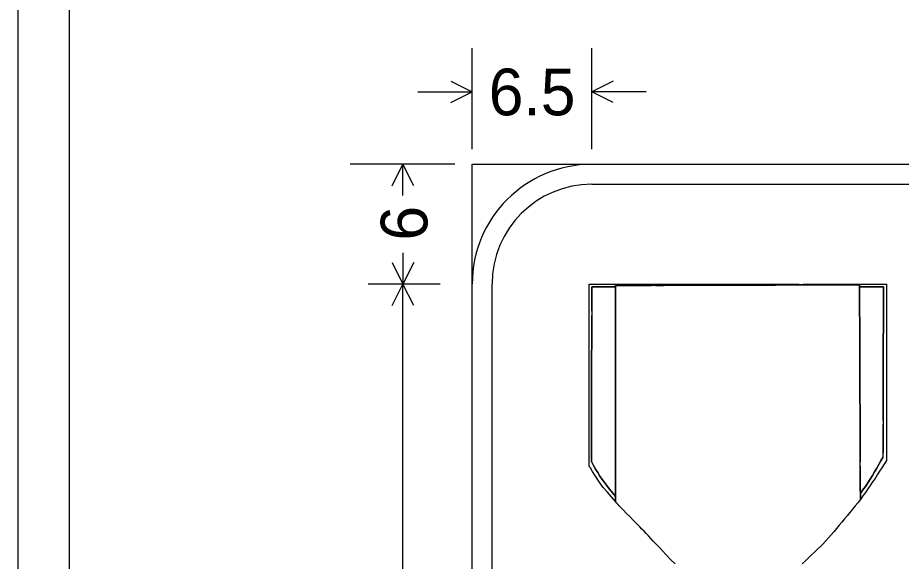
# Model space of a CAD drawing. Extents: x 187716 to 188418, y 178603 to 179533.
# Drawn here: x 187716 to 187905.3, y 179178.8 to 179295.2 of the extents above; entities that cross this region are included whole.
import ezdxf

# ---------------------------------------------------------------- set-up
doc = ezdxf.new("R2010")
doc.units = 0
doc.layers.add('Default', color=7, linetype='Continuous')

msp = doc.modelspace()

# ---------------------------------------------------------------- linework, layer by layer
at = {"layer": 'Default'}
for p, q in [((187813.36, 179267.08), (187813.36, 179288.69)), ((187839, 179267.08), (187839, 179288.69)), ((187808.77, 179281.65), (187813.36, 179279.35)), ((187843.59, 179281.65), (187839, 179279.35)), ((187801.71, 179279.35), (187813.36, 179279.35)), ((187808.77, 179277.06), (187813.36, 179279.35)), ((187850.64, 179279.35), (187839, 179279.35)), ((187843.59, 179277.06), (187839, 179279.35)), ((187809.67, 179263.83), (187787.24, 179263.83)), ((187806.47, 179263.83), (187791.08, 179263.83)), ((187796.24, 179259.24), (187798.53, 179263.83)), ((187798.53, 179257.15), (187798.53, 179263.83)), ((187800.83, 179259.24), (187798.53, 179263.83)), ((187813.36, 179263.83), (188326.2, 179263.83)), ((187813.36, 179058.69), (187813.36, 179263.83)), ((187839, 179263.83), (188300.55, 179263.83)), ((187839, 179259.55), (188300.55, 179259.55)), ((187798.53, 179244.86), (187798.53, 179238.18)), ((187796.24, 179242.77), (187798.53, 179238.18)), ((187800.83, 179242.77), (187798.53, 179238.18)), ((187806.47, 179238.18), (187791.08, 179238.18)), ((187796.24, 179233.6), (187798.53, 179238.18)), ((187798.53, 179173.47), (187798.53, 179238.18)), ((187800.83, 179233.6), (187798.53, 179238.18)), ((187813.36, 179084.33), (187813.36, 179238.18)), ((187817.63, 179084.33), (187817.63, 179238.18))]:
    msp.add_line(p, q, dxfattribs=at)
for points in [[(188418.09, 178602.69), (188418.09, 179533.02), (187715.97, 179533.02), (187715.97, 178602.69)], [(188407.12, 178613.73), (188407.12, 179522.02), (187727.02, 179522.02), (187727.02, 178613.73)], [(187813.36, 179263.83), (188326.2, 179263.83), (188326.2, 179058.69), (187813.36, 179058.69)]]:
    msp.add_lwpolyline(points, close=True, dxfattribs=at)
for points in [[(187838.46, 179199.13), (187838.46, 179199.99), (187838.46, 179200.86), (187838.46, 179201.73), (187838.46, 179202.6), (187838.46, 179203.47), (187838.46, 179204.34), (187838.46, 179205.2), (187838.46, 179206.07), (187838.46, 179206.94), (187838.46, 179207.81), (187838.46, 179208.68), (187838.46, 179209.54), (187838.46, 179210.41), (187838.46, 179211.28), (187838.46, 179212.15), (187838.46, 179213.02), (187838.46, 179213.88), (187838.46, 179214.75), (187838.46, 179215.62), (187838.46, 179216.49), (187838.46, 179217.36), (187838.46, 179218.22), (187838.46, 179219.09), (187838.46, 179219.96), (187838.46, 179220.83), (187838.46, 179221.7), (187838.46, 179222.56), (187838.46, 179223.43), (187838.46, 179224.3), (187838.46, 179225.17), (187838.46, 179226.04), (187838.46, 179226.9), (187838.46, 179227.77), (187838.46, 179228.64), (187838.46, 179229.51), (187838.46, 179230.37), (187838.46, 179231.24), (187838.46, 179232.11), (187838.46, 179232.98), (187838.46, 179233.85), (187838.46, 179234.71), (187838.46, 179235.58), (187838.46, 179236.45), (187838.46, 179237.32), (187838.46, 179238.18), (187838.46, 179238.18), (187839.3, 179238.18), (187840.15, 179238.18), (187841, 179238.18), (187841.85, 179238.18), (187842.7, 179238.18), (187843.55, 179238.18), (187844.4, 179238.18), (187845.24, 179238.18), (187846.09, 179238.18), (187846.94, 179238.18), (187847.79, 179238.18), (187848.64, 179238.18), (187849.49, 179238.18), (187850.33, 179238.18), (187851.18, 179238.18), (187852.03, 179238.18), (187852.88, 179238.18), (187853.73, 179238.18), (187854.58, 179238.18), (187855.43, 179238.18), (187856.27, 179238.18), (187857.12, 179238.18), (187857.97, 179238.18), (187858.82, 179238.18), (187859.67, 179238.18), (187860.52, 179238.18), (187861.37, 179238.18), (187862.21, 179238.18), (187863.06, 179238.18), (187863.91, 179238.18), (187864.76, 179238.18), (187865.61, 179238.18), (187866.46, 179238.18), (187867.31, 179238.18), (187868.16, 179238.18), (187869, 179238.18), (187869.85, 179238.18), (187870.7, 179238.18), (187871.55, 179238.18), (187872.4, 179238.18), (187873.25, 179238.18), (187874.1, 179238.18), (187874.94, 179238.18), (187875.79, 179238.18), (187876.64, 179238.18), (187877.49, 179238.18), (187878.34, 179238.18), (187879.19, 179238.18), (187880.04, 179238.18), (187880.89, 179238.18), (187881.73, 179238.18), (187882.58, 179238.18), (187883.43, 179238.18)], [(187846.67, 179237.89), (187845.81, 179237.89), (187844.96, 179237.88), (187844.1, 179237.88), (187844.1, 179237.88), (187844.1, 179237.78), (187844.1, 179237.67), (187844.1, 179237.57), (187843.08, 179237.57), (187842.06, 179237.57), (187841.03, 179237.57), (187840.02, 179237.57), (187839, 179237.57), (187838.99, 179236.7), (187838.99, 179235.83), (187838.99, 179234.96), (187838.99, 179234.09), (187838.99, 179233.23), (187838.98, 179232.36), (187838.98, 179231.49), (187838.98, 179230.62), (187838.98, 179229.75), (187838.98, 179228.88), (187838.97, 179228.01), (187838.97, 179227.14), (187838.97, 179226.28), (187838.97, 179225.41), (187838.97, 179224.54), (187838.96, 179223.67), (187838.96, 179222.8), (187838.96, 179221.93), (187838.96, 179221.06), (187838.96, 179220.19), (187838.95, 179219.33), (187838.95, 179218.46), (187838.95, 179217.59), (187838.95, 179216.72), (187838.95, 179215.85), (187838.94, 179214.98), (187838.94, 179214.11), (187838.94, 179213.24), (187838.94, 179212.37), (187838.94, 179211.5), (187838.93, 179210.64), (187838.93, 179209.77), (187838.93, 179208.9), (187838.93, 179208.03), (187838.93, 179207.16), (187838.92, 179206.29), (187838.92, 179205.42), (187838.92, 179204.55), (187838.92, 179203.68), (187838.92, 179202.81), (187838.91, 179201.95), (187838.91, 179201.08), (187838.91, 179200.21), (187838.91, 179200.21), (187839.35, 179199.38), (187839.8, 179198.58), (187840.27, 179197.82), (187840.75, 179197.07), (187841.24, 179196.34), (187841.76, 179195.63), (187842.3, 179194.91), (187842.87, 179194.19), (187843.47, 179193.45), (187844.1, 179192.7), (187844.1, 179192.34), (187844.1, 179191.98), (187844.1, 179191.62), (187843.22, 179192.63), (187842.34, 179193.63), (187841.46, 179194.64), (187840.6, 179195.84), (187839.81, 179197.04), (187839.16, 179198.08), (187838.69, 179198.82), (187838.46, 179199.13)], [(187844.1, 179237.57), (187844.1, 179236.71), (187844.1, 179235.84), (187844.1, 179234.98), (187844.1, 179234.12), (187844.1, 179233.26), (187844.1, 179232.39), (187844.1, 179231.53), (187844.1, 179230.67), (187844.1, 179229.8), (187844.1, 179228.94), (187844.1, 179228.08), (187844.1, 179227.22), (187844.1, 179226.35), (187844.1, 179225.49), (187844.1, 179224.63), (187844.1, 179223.77), (187844.1, 179222.9), (187844.1, 179222.04), (187844.1, 179221.18), (187844.1, 179220.32), (187844.1, 179219.45), (187844.1, 179218.59), (187844.1, 179217.73), (187844.1, 179216.86), (187844.1, 179216), (187844.1, 179215.14), (187844.1, 179214.28), (187844.1, 179213.41), (187844.1, 179212.55), (187844.1, 179211.69), (187844.1, 179210.82), (187844.1, 179209.96), (187844.1, 179209.1), (187844.1, 179208.24), (187844.1, 179207.37), (187844.1, 179206.51), (187844.1, 179205.65), (187844.1, 179204.78), (187844.1, 179203.92), (187844.1, 179203.06), (187844.1, 179202.2), (187844.1, 179201.33), (187844.1, 179200.47), (187844.1, 179199.61), (187844.1, 179198.74), (187844.1, 179197.88), (187844.1, 179197.02), (187844.1, 179196.15), (187844.1, 179195.29), (187844.1, 179194.43), (187844.1, 179193.57), (187844.1, 179192.7), (187844.1, 179192.7), (187843.47, 179193.45), (187842.87, 179194.19), (187842.3, 179194.91), (187841.76, 179195.63), (187841.24, 179196.34), (187840.75, 179197.07), (187840.27, 179197.82), (187839.8, 179198.58), (187839.35, 179199.38), (187838.91, 179200.21), (187838.91, 179201.08), (187838.91, 179201.95), (187838.92, 179202.81), (187838.92, 179203.68), (187838.92, 179204.55), (187838.92, 179205.42), (187838.92, 179206.29), (187838.93, 179207.16), (187838.93, 179208.03), (187838.93, 179208.9), (187838.93, 179209.77), (187838.93, 179210.64), (187838.94, 179211.5), (187838.94, 179212.37), (187838.94, 179213.24), (187838.94, 179214.11), (187838.94, 179214.98), (187838.95, 179215.85), (187838.95, 179216.72), (187838.95, 179217.59), (187838.95, 179218.46), (187838.95, 179219.33), (187838.96, 179220.19), (187838.96, 179221.06), (187838.96, 179221.93), (187838.96, 179222.8), (187838.96, 179223.67), (187838.97, 179224.54), (187838.97, 179225.41), (187838.97, 179226.28), (187838.97, 179227.14), (187838.97, 179228.01), (187838.98, 179228.88), (187838.98, 179229.75), (187838.98, 179230.62), (187838.98, 179231.49)], [(187838.98, 179232.36), (187838.99, 179233.23), (187838.99, 179234.09), (187838.99, 179234.96), (187838.99, 179235.83), (187838.99, 179236.7), (187839, 179237.57), (187839, 179237.57), (187840.01, 179237.57), (187841.03, 179237.57), (187842.05, 179237.57), (187843.08, 179237.57), (187844.1, 179237.57)], [(187856.83, 179178.32), (187855.86, 179179.25), (187854.95, 179180.21), (187854.14, 179181.08), (187853.42, 179181.85), (187852.76, 179182.54), (187852.17, 179183.17), (187851.63, 179183.75), (187851.12, 179184.28), (187850.65, 179184.78), (187850.18, 179185.26), (187849.73, 179185.74), (187849.26, 179186.22), (187848.78, 179186.71), (187848.27, 179187.24), (187847.71, 179187.8), (187847.11, 179188.42), (187846.44, 179189.1), (187845.7, 179189.85), (187844.87, 179190.69), (187844.87, 179190.69), (187844.61, 179191), (187844.36, 179191.31), (187844.1, 179191.62), (187844.1, 179191.98), (187844.1, 179192.34), (187844.1, 179192.7), (187844.1, 179193.57), (187844.1, 179194.43), (187844.1, 179195.29), (187844.1, 179196.15), (187844.1, 179197.02), (187844.1, 179197.88), (187844.1, 179198.74), (187844.1, 179199.61), (187844.1, 179200.47), (187844.1, 179201.33), (187844.1, 179202.2), (187844.1, 179203.06), (187844.1, 179203.92), (187844.1, 179204.78), (187844.1, 179205.65), (187844.1, 179206.51), (187844.1, 179207.37), (187844.1, 179208.24), (187844.1, 179209.1), (187844.1, 179209.96), (187844.1, 179210.82), (187844.1, 179211.69), (187844.1, 179212.55), (187844.1, 179213.41), (187844.1, 179214.28), (187844.1, 179215.14), (187844.1, 179216), (187844.1, 179216.86), (187844.1, 179217.73), (187844.1, 179218.59), (187844.1, 179219.45), (187844.1, 179220.32), (187844.1, 179221.18), (187844.1, 179222.04), (187844.1, 179222.9), (187844.1, 179223.77), (187844.1, 179224.63), (187844.1, 179225.49), (187844.1, 179226.35), (187844.1, 179227.22), (187844.1, 179228.08), (187844.1, 179228.94), (187844.1, 179229.8), (187844.1, 179230.67), (187844.1, 179231.53), (187844.1, 179232.39), (187844.1, 179233.26), (187844.1, 179234.12), (187844.1, 179234.98), (187844.1, 179235.84), (187844.1, 179236.71), (187844.1, 179237.57), (187844.1, 179237.57), (187844.1, 179237.67), (187844.1, 179237.78), (187844.1, 179237.88), (187844.96, 179237.88), (187845.81, 179237.89), (187846.67, 179237.89), (187847.53, 179237.89), (187848.38, 179237.9), (187849.24, 179237.9), (187850.1, 179237.9), (187850.95, 179237.9), (187851.81, 179237.91)], [(187901.42, 179209.01), (187901.42, 179209.87), (187901.43, 179210.74), (187901.43, 179211.6), (187901.43, 179212.47), (187901.43, 179213.33), (187901.43, 179214.2), (187901.44, 179215.07), (187901.44, 179215.93), (187901.44, 179216.8), (187901.44, 179217.66), (187901.44, 179218.53), (187901.45, 179219.39), (187901.45, 179220.26), (187901.45, 179221.12), (187901.45, 179221.99), (187901.45, 179222.86), (187901.46, 179223.72), (187901.46, 179224.59), (187901.46, 179225.45), (187901.46, 179226.32), (187901.46, 179227.18), (187901.47, 179228.05), (187901.47, 179228.91), (187901.47, 179229.78), (187901.47, 179230.65), (187901.48, 179231.51), (187901.48, 179232.38), (187901.48, 179233.24), (187901.48, 179234.11), (187901.48, 179234.97), (187901.48, 179235.84), (187901.49, 179236.7), (187901.49, 179237.57), (187901.49, 179237.57), (187900.46, 179237.57), (187899.44, 179237.57), (187898.42, 179237.57), (187897.4, 179237.57), (187896.38, 179237.57), (187896.38, 179237.73), (187896.38, 179237.88), (187896.38, 179238.03), (187895.52, 179238.03), (187894.66, 179238.03), (187893.8, 179238.03), (187892.95, 179238.02), (187892.09, 179238.02), (187891.23, 179238.02), (187890.38, 179238.02), (187889.52, 179238.01), (187888.66, 179238.01), (187887.8, 179238.01), (187886.95, 179238.01), (187886.09, 179238.01), (187885.23, 179238), (187884.38, 179238), (187883.52, 179238), (187882.66, 179238), (187881.8, 179237.99), (187880.95, 179237.99), (187880.09, 179237.99), (187879.23, 179237.99), (187878.38, 179237.98), (187877.52, 179237.98), (187876.66, 179237.98), (187875.81, 179237.98), (187874.95, 179237.97), (187874.09, 179237.97), (187873.23, 179237.97), (187872.38, 179237.97), (187871.52, 179237.96), (187870.66, 179237.96), (187869.81, 179237.96), (187868.95, 179237.96), (187868.09, 179237.95), (187867.23, 179237.95), (187866.38, 179237.95), (187865.52, 179237.95), (187864.66, 179237.94), (187863.81, 179237.94), (187862.95, 179237.94), (187862.09, 179237.94), (187861.24, 179237.93), (187860.38, 179237.93), (187859.52, 179237.93), (187858.67, 179237.93), (187857.81, 179237.92), (187856.95, 179237.92), (187856.09, 179237.92), (187855.24, 179237.92), (187854.38, 179237.91), (187853.52, 179237.91), (187852.67, 179237.91), (187851.81, 179237.91), (187850.95, 179237.9), (187850.1, 179237.9), (187849.24, 179237.9), (187848.38, 179237.9), (187847.53, 179237.89)], [(187852.67, 179237.91), (187853.52, 179237.91), (187854.38, 179237.91), (187855.24, 179237.92), (187856.09, 179237.92), (187856.95, 179237.92), (187857.81, 179237.92), (187858.67, 179237.93), (187859.52, 179237.93), (187860.38, 179237.93), (187861.24, 179237.93), (187862.09, 179237.94), (187862.95, 179237.94), (187863.81, 179237.94), (187864.66, 179237.94), (187865.52, 179237.95), (187866.38, 179237.95), (187867.23, 179237.95), (187868.09, 179237.95), (187868.95, 179237.96), (187869.81, 179237.96), (187870.66, 179237.96), (187871.52, 179237.96), (187872.38, 179237.97), (187873.23, 179237.97), (187874.09, 179237.97), (187874.95, 179237.97), (187875.81, 179237.98), (187876.66, 179237.98), (187877.52, 179237.98), (187878.38, 179237.98), (187879.23, 179237.99), (187880.09, 179237.99), (187880.95, 179237.99), (187881.8, 179237.99), (187882.66, 179238), (187883.52, 179238), (187884.38, 179238), (187885.23, 179238), (187886.09, 179238.01), (187886.95, 179238.01), (187887.8, 179238.01), (187888.66, 179238.01), (187889.52, 179238.01), (187890.38, 179238.02), (187891.23, 179238.02), (187892.09, 179238.02), (187892.95, 179238.02), (187893.8, 179238.03), (187894.66, 179238.03), (187895.52, 179238.03), (187896.38, 179238.03), (187896.38, 179238.03), (187896.38, 179237.88), (187896.38, 179237.73), (187896.38, 179237.57), (187896.38, 179236.72), (187896.38, 179235.87), (187896.38, 179235.02), (187896.39, 179234.17), (187896.39, 179233.31), (187896.39, 179232.46), (187896.39, 179231.61), (187896.4, 179230.76), (187896.4, 179229.91), (187896.4, 179229.06), (187896.41, 179228.21), (187896.41, 179227.36), (187896.41, 179226.51), (187896.42, 179225.66), (187896.42, 179224.81), (187896.42, 179223.96), (187896.42, 179223.11), (187896.43, 179222.25), (187896.43, 179221.4), (187896.43, 179220.55), (187896.44, 179219.7), (187896.44, 179218.85), (187896.44, 179218), (187896.45, 179217.15), (187896.45, 179216.3), (187896.45, 179215.45), (187896.46, 179214.6), (187896.46, 179213.75), (187896.46, 179212.89), (187896.47, 179212.04), (187896.47, 179211.19), (187896.47, 179210.34), (187896.47, 179209.49), (187896.48, 179208.64), (187896.48, 179207.79), (187896.48, 179206.94), (187896.49, 179206.09), (187896.49, 179205.24), (187896.49, 179204.38), (187896.5, 179203.53), (187896.5, 179202.68), (187896.5, 179201.83), (187896.51, 179200.98), (187896.51, 179200.13)], [(187884.28, 179238.18), (187885.13, 179238.18), (187885.98, 179238.18), (187886.83, 179238.18), (187887.68, 179238.18), (187888.52, 179238.18), (187889.37, 179238.18), (187890.22, 179238.18), (187891.07, 179238.18), (187891.92, 179238.18), (187892.77, 179238.18), (187893.62, 179238.18), (187894.47, 179238.18), (187895.31, 179238.18), (187896.16, 179238.18), (187897.01, 179238.18), (187897.86, 179238.18), (187898.71, 179238.18), (187899.56, 179238.18), (187900.41, 179238.18), (187901.26, 179238.18), (187902.11, 179238.18), (187902.11, 179238.18), (187902.11, 179237.33), (187902.11, 179236.47), (187902.11, 179235.61), (187902.11, 179234.75), (187902.11, 179233.9), (187902.11, 179233.04), (187902.11, 179232.18), (187902.11, 179231.32), (187902.11, 179230.46), (187902.11, 179229.61), (187902.11, 179228.75), (187902.11, 179227.89), (187902.11, 179227.03), (187902.11, 179226.18), (187902.11, 179225.32), (187902.11, 179224.46), (187902.11, 179223.6), (187902.11, 179222.75), (187902.11, 179221.89), (187902.11, 179221.03), (187902.11, 179220.17), (187902.11, 179219.31), (187902.11, 179218.46), (187902.11, 179217.6), (187902.11, 179216.74), (187902.11, 179215.88), (187902.11, 179215.03), (187902.11, 179214.17), (187902.11, 179213.31), (187902.11, 179212.45), (187902.11, 179211.59), (187902.11, 179210.74), (187902.11, 179209.88), (187902.11, 179209.02), (187902.11, 179208.16), (187902.11, 179207.31), (187902.11, 179206.45), (187902.11, 179205.59), (187902.11, 179204.73), (187902.11, 179203.88), (187902.11, 179203.02), (187902.11, 179202.16), (187902.11, 179201.3), (187902.11, 179200.44), (187902.11, 179200.44), (187901.63, 179199.66), (187901.15, 179198.88), (187900.66, 179198.11), (187900.17, 179197.34), (187899.68, 179196.59), (187899.17, 179195.83), (187898.66, 179195.08), (187898.14, 179194.33), (187897.62, 179193.58), (187897.08, 179192.84), (187896.54, 179192.09), (187896.54, 179192.5), (187896.54, 179192.91), (187896.54, 179193.32), (187897.08, 179194.11), (187897.61, 179194.88), (187898.12, 179195.65), (187898.62, 179196.42), (187899.11, 179197.19), (187899.59, 179197.96), (187900.06, 179198.75), (187900.51, 179199.55), (187900.96, 179200.37), (187901.4, 179201.21), (187901.41, 179202.08), (187901.41, 179202.94), (187901.41, 179203.81), (187901.41, 179204.68), (187901.41, 179205.54), (187901.42, 179206.41), (187901.42, 179207.27), (187901.42, 179208.14)], [(187896.54, 179193.32), (187896.53, 179194.17), (187896.53, 179195.02), (187896.53, 179195.87), (187896.52, 179196.72), (187896.52, 179197.58), (187896.52, 179198.43), (187896.51, 179199.28), (187896.51, 179200.13), (187896.51, 179200.98), (187896.5, 179201.83), (187896.5, 179202.68), (187896.5, 179203.53), (187896.49, 179204.38), (187896.49, 179205.24), (187896.49, 179206.09), (187896.48, 179206.94), (187896.48, 179207.79), (187896.48, 179208.64), (187896.47, 179209.49), (187896.47, 179210.34), (187896.47, 179211.19), (187896.47, 179212.04), (187896.46, 179212.89), (187896.46, 179213.75), (187896.46, 179214.6), (187896.45, 179215.45), (187896.45, 179216.3), (187896.45, 179217.15), (187896.44, 179218), (187896.44, 179218.85), (187896.44, 179219.7), (187896.43, 179220.55), (187896.43, 179221.4), (187896.43, 179222.25), (187896.42, 179223.11), (187896.42, 179223.96), (187896.42, 179224.81), (187896.42, 179225.66), (187896.41, 179226.51), (187896.41, 179227.36), (187896.41, 179228.21), (187896.4, 179229.06), (187896.4, 179229.91), (187896.4, 179230.76), (187896.39, 179231.61), (187896.39, 179232.46), (187896.39, 179233.31), (187896.39, 179234.17), (187896.38, 179235.02), (187896.38, 179235.87), (187896.38, 179236.72), (187896.38, 179237.57), (187896.38, 179237.57), (187897.4, 179237.57), (187898.42, 179237.57), (187899.44, 179237.57), (187900.46, 179237.57), (187901.49, 179237.57), (187901.49, 179236.7), (187901.48, 179235.84), (187901.48, 179234.97), (187901.48, 179234.11), (187901.48, 179233.24), (187901.48, 179232.38), (187901.48, 179231.51), (187901.47, 179230.65), (187901.47, 179229.78), (187901.47, 179228.91), (187901.47, 179228.05), (187901.46, 179227.18), (187901.46, 179226.32), (187901.46, 179225.45), (187901.46, 179224.59), (187901.46, 179223.72), (187901.45, 179222.86), (187901.45, 179221.99), (187901.45, 179221.12), (187901.45, 179220.26), (187901.45, 179219.39), (187901.44, 179218.53), (187901.44, 179217.66), (187901.44, 179216.8), (187901.44, 179215.93), (187901.44, 179215.07), (187901.43, 179214.2), (187901.43, 179213.33), (187901.43, 179212.47), (187901.43, 179211.6), (187901.43, 179210.74), (187901.42, 179209.87), (187901.42, 179209.01), (187901.42, 179208.14), (187901.42, 179207.27), (187901.42, 179206.41), (187901.41, 179205.54), (187901.41, 179204.68), (187901.41, 179203.81), (187901.41, 179202.94), (187901.41, 179202.08)], [(187901.4, 179201.21), (187901.4, 179201.21), (187900.96, 179200.37), (187900.51, 179199.55), (187900.06, 179198.75), (187899.59, 179197.96), (187899.11, 179197.19), (187898.62, 179196.42), (187898.12, 179195.65), (187897.61, 179194.88), (187897.08, 179194.11), (187896.54, 179193.32)], [(187896.51, 179199.28), (187896.52, 179198.43), (187896.52, 179197.57), (187896.52, 179196.72), (187896.53, 179195.87), (187896.53, 179195.02), (187896.53, 179194.17), (187896.54, 179193.32), (187896.54, 179193.32), (187896.54, 179192.91), (187896.54, 179192.5), (187896.54, 179192.09), (187895.98, 179191.39), (187895.42, 179190.69), (187894.86, 179189.99), (187894.3, 179189.3), (187893.73, 179188.6), (187893.17, 179187.91), (187892.6, 179187.23), (187892.03, 179186.54), (187891.45, 179185.86), (187890.87, 179185.18), (187890.28, 179184.5), (187889.69, 179183.83), (187889.1, 179183.16), (187888.49, 179182.49), (187887, 179181.07), (187885.8, 179179.92), (187884.84, 179179), (187884.09, 179178.27)]]:
    msp.add_lwpolyline(points, dxfattribs=at)
for radius in [25.64, 21.37]:
    msp.add_arc((187839, 179238.18), radius, 90, 180, dxfattribs=at)

# ---------------------------------------------------------------- texts
msp.add_text('6.5', height=10, dxfattribs=at).set_placement((187816.91, 179274.31))
msp.add_text('6', height=10, rotation=90, dxfattribs=at).set_placement((187803.77, 179247.49))

doc.saveas('drawing.dxf')
